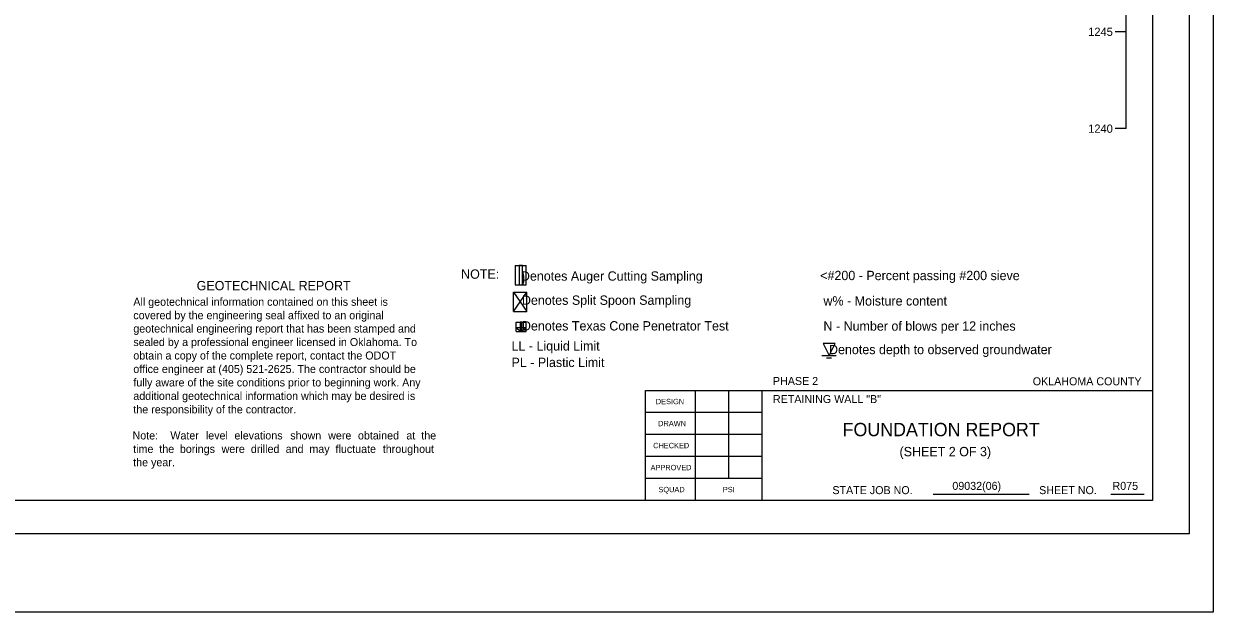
# Model space of a CAD drawing. Extents: x 7 to 126, y 24 to 56.
# Drawn here: x 66.46 to 84.3, y 29.97 to 38.8 of the extents above; entities that cross this region are included whole.
import ezdxf

# ---------------------------------------------------------------- set-up
doc = ezdxf.new("R2010")
doc.units = 0
for name, color, linetype in [('4', 7, 'Continuous'), ('SHT_Plot_Shape_Full', 7, 'Continuous'), ('SHT_Plot_Shape_Half', 7, 'Continuous'), ('SHT_Sheet_Border', 7, 'Continuous'), ('SHT_Standard_Sheet_Lines', 7, 'Continuous'), ('SHT_Standard_Sheet_Txt', 7, 'Continuous'), ('T', 7, 'Continuous'), ('T-5', 7, 'Continuous'), ('Text', 7, 'Continuous')]:
    doc.layers.add(name, color=color, linetype=linetype)

# ---------------------------------------------------------------- blocks, each defined once
blk = doc.blocks.new('DGRFC_WTLEV1_1')
for points in [[(0, 0), (0.00417, 0.00833), (-0.00417, 0.00833), (0, 0)], [(-0.005, 0), (0.005, 0)], [(-0.00167, -0.00167), (0.00167, -0.00167)]]:
    blk.add_lwpolyline(points)

msp = doc.modelspace()

# ---------------------------------------------------------------- linework, layer by layer
for p, q in [((82.998, 37.223), (82.998, 50.304)), ((73.832, 35.172), (73.832, 34.881))]:
    msp.add_line(p, q)
for points in [[(82.998, 38.676), (82.831, 38.676)], [(82.998, 37.223), (82.831, 37.223)], [(73.832, 35.172), (73.999, 35.172)], [(73.999, 34.881), (73.999, 35.172)], [(73.832, 34.881), (73.999, 34.881)], [(73.832, 34.881), (73.999, 34.881)]]:
    msp.add_lwpolyline(points)
for points in [[(73.891, 35.172), (73.891, 34.881), (73.941, 34.881), (73.941, 35.172)], [(73.955, 35.005), (73.949, 35.047), (73.941, 35.087), (73.955, 35.005)], [(73.941, 35.087), (73.941, 34.881), (73.955, 35.005), (73.941, 35.087)], [(73.941, 34.881), (73.955, 34.922), (73.955, 35.005), (73.941, 34.881)], [(73.955, 34.922), (73.957, 34.963), (73.955, 35.005), (73.955, 34.922)], [(73.941, 34.881), (73.949, 34.881), (73.955, 34.922), (73.941, 34.881)]]:
    msp.add_lwpolyline(points, close=True)
at = {"layer": 'SHT_Plot_Shape_Full'}
msp.add_lwpolyline([(48.302, 53.971), (84.302, 53.971), (84.302, 29.971), (48.302, 29.971)], close=True, dxfattribs=at)
at = {"layer": 'SHT_Plot_Shape_Half'}
msp.add_lwpolyline([(49.939, 53.146), (83.939, 53.146), (83.939, 31.146), (49.939, 31.146)], close=True, dxfattribs=at)
at = {"layer": 'SHT_Sheet_Border'}
for p, q in [((75.789, 31.646), (75.789, 33.296)), ((75.789, 33.296), (83.389, 33.296)), ((77.539, 31.646), (77.539, 33.297))]:
    msp.add_line(p, q, dxfattribs=at)
msp.add_lwpolyline([(51.889, 52.646), (83.389, 52.646), (83.389, 31.646), (51.889, 31.646)], close=True, dxfattribs=at)
at = {"layer": 'SHT_Standard_Sheet_Lines'}
for p, q in [((76.539, 31.646), (76.539, 33.297)), ((77.039, 31.976), (77.039, 33.297)), ((80.1, 31.742), (81.54, 31.742)), ((82.765, 31.742), (83.267, 31.742))]:
    msp.add_line(p, q, dxfattribs=at)
for points in [[(77.539, 32.966), (75.789, 32.966)], [(77.539, 32.636), (75.789, 32.636)], [(77.539, 32.306), (75.789, 32.306)], [(77.539, 31.976), (75.789, 31.976)]]:
    msp.add_lwpolyline(points, dxfattribs=at)
at = {"layer": 'Text'}
for p, q in [((73.809, 34.481), (73.809, 34.773)), ((73.845, 34.181), (73.845, 34.322))]:
    msp.add_line(p, q, dxfattribs=at)
for points in [[(73.809, 34.481), (74.009, 34.773)], [(73.809, 34.773), (74.009, 34.481)], [(73.809, 34.773), (74.009, 34.773)], [(74.009, 34.481), (74.009, 34.773)], [(73.809, 34.481), (74.009, 34.481)], [(73.845, 34.322), (73.995, 34.322)], [(73.995, 34.181), (73.995, 34.322)], [(73.845, 34.181), (73.995, 34.181)]]:
    msp.add_lwpolyline(points, dxfattribs=at)
for points in [[(73.905, 34.237), (73.935, 34.322), (73.905, 34.322), (73.905, 34.237)], [(73.905, 34.237), (73.935, 34.237), (73.935, 34.322), (73.905, 34.237)], [(73.905, 34.237), (73.845, 34.237), (73.92, 34.181), (73.905, 34.237)], [(73.905, 34.237), (73.92, 34.181), (73.935, 34.237), (73.905, 34.237)], [(73.92, 34.181), (73.995, 34.237), (73.935, 34.237), (73.92, 34.181)]]:
    msp.add_lwpolyline(points, close=True, dxfattribs=at)

# ---------------------------------------------------------------- block references
at = {"layer": 'Text', "xscale": 21.6, "yscale": 21.6}
msp.add_blockref('DGRFC_WTLEV1_1', (78.54, 33.823), dxfattribs=at)

# ---------------------------------------------------------------- texts
for s, p in [('1245', (82.427, 38.614)), ('1240', (82.427, 37.161))]:
    msp.add_text(s, height=0.124).set_placement(p)
at = {"layer": '4'}
msp.add_text('FOUNDATION REPORT', height=0.2, dxfattribs=at).set_placement((78.743, 32.611))
at = {"layer": 'SHT_Standard_Sheet_Txt'}
for s, height, p in [('DESIGN', 0.08, (75.942, 33.091)), ('DRAWN', 0.08, (75.977, 32.761)), ('CHECKED', 0.08, (75.902, 32.431)), ('APPROVED', 0.08, (75.863, 32.101)), ('SQUAD', 0.08, (75.981, 31.771)), ('PSI', 0.08, (76.947, 31.771)), ('STATE JOB NO.', 0.12, (78.59, 31.742)), ('SHEET NO. ', 0.12, (81.691, 31.742))]:
    msp.add_text(s, height=height, dxfattribs=at).set_placement(p)
at = {"layer": 'T'}
for s, p in [('PHASE 2', (77.698, 33.379)), ('OKLAHOMA COUNTY', (81.595, 33.374)), ('RETAINING WALL "B" ', (77.698, 33.108)), ('09032(06)', (80.389, 31.806)), ('R075', (82.791, 31.806))]:
    msp.add_text(s, height=0.12, dxfattribs=at).set_placement(p)
at = {"layer": 'T-5'}
msp.add_text('(SHEET 2 OF 3)', height=0.14, dxfattribs=at).set_placement((79.597, 32.31))
at = {"layer": 'Text'}
for s, height, p in [('NOTE:', 0.14, (73.021, 34.972)), ('    Denotes Auger Cutting Sampling', 0.14, (73.71, 34.943)), (' <#200 - Percent passing #200 sieve', 0.14, (78.355, 34.951)), ('GEOTECHNICAL REPORT', 0.14, (69.055, 34.799)), ('All geotechnical information contained on this sheet is ', 0.12, (68.105, 34.567)), ('    Denotes Split Spoon Sampling', 0.14, (73.725, 34.581)), ('w% - Moisture content', 0.14, (78.456, 34.57)), ('covered by the engineering seal affixed to an original ', 0.12, (68.105, 34.365)), ('geotechnical engineering report that has been stamped and ', 0.12, (68.105, 34.165)), ('    Denotes Texas Cone Penetrator Test', 0.14, (73.725, 34.196)), ('N - Number of blows per 12 inches', 0.14, (78.456, 34.193)), ('sealed by a professional engineer licensed in Oklahoma. To ', 0.12, (68.105, 33.963)), (' LL - Liquid Limit', 0.14, (73.725, 33.895)), ('    Denotes depth to observed groundwater', 0.14, (78.331, 33.841)), ('obtain a copy of the complete report, contact the ODOT ', 0.12, (68.105, 33.761)), (' PL - Plastic Limit', 0.14, (73.725, 33.648)), ('office engineer at (405) 521-2625. The contractor should be ', 0.12, (68.105, 33.559)), ('fully aware of the site conditions prior to beginning work. Any ', 0.12, (68.105, 33.357)), ('additional geotechnical information which may be desired is ', 0.12, (68.105, 33.155)), ('the responsibility of the contractor.', 0.12, (68.105, 32.953)), ('Note:', 0.12, (68.093, 32.562)), ('Water', 0.12, (68.66, 32.562)), ('level', 0.12, (69.193, 32.562)), ('elevations', 0.12, (69.621, 32.562)), ('shown', 0.12, (70.459, 32.562)), ('were', 0.12, (71.027, 32.562)), ('obtained', 0.12, (71.474, 32.562)), ('at', 0.12, (72.2, 32.562)), ('the ', 0.12, (72.424, 32.562)), ('time', 0.12, (68.103, 32.36)), ('the', 0.12, (68.495, 32.36)), ('borings', 0.12, (68.803, 32.36)), ('drilled', 0.12, (69.868, 32.36)), ('and', 0.12, (70.39, 32.36)), ('fluctuate', 0.12, (71.138, 32.36)), ('throughout ', 0.12, (71.847, 32.36)), ('were', 0.12, (69.429, 32.36)), ('may', 0.12, (70.746, 32.36)), ('the year.', 0.12, (68.103, 32.16))]:
    msp.add_text(s, height=height, dxfattribs=at).set_placement(p)

doc.saveas('drawing.dxf')
